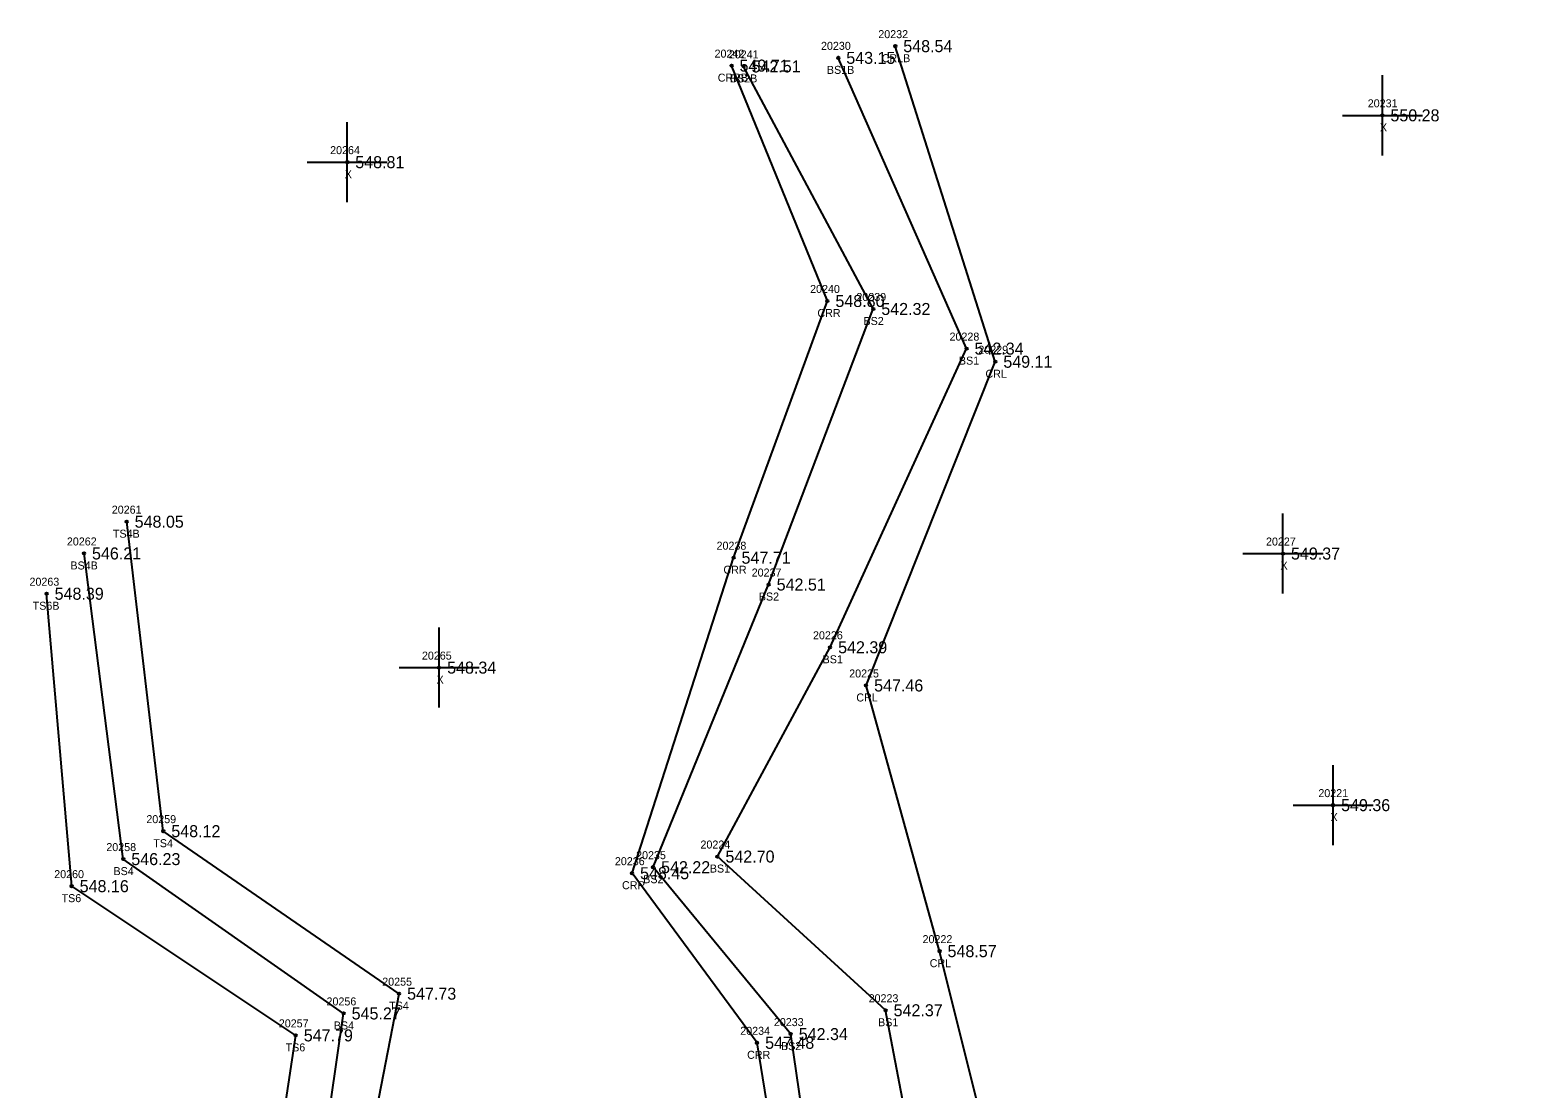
# Model space of a CAD drawing. Extents: x 1540443 to 1541844, y 887157 to 888162.
# Drawn here: x 1540987 to 1541174.7, y 888029.8 to 888162.1 of the extents above; entities that cross this region are included whole.
import ezdxf

# ---------------------------------------------------------------- set-up
doc = ezdxf.new("R2010")
doc.units = 0
for name, color, linetype in [('RD_DTM_BkLn2', 7, 'Continuous'), ('RD_DTM_BkLn_txCode', 7, 'Continuous'), ('RD_EX_H2O', 7, 'Continuous'), ('RD_EX_H2O_txCode', 7, 'Continuous'), ('RD_EX_Misc', 7, 'Continuous'), ('RD_EX_Misc_txCode', 7, 'Continuous'), ('RD_EX_TX_H2O_ELEV', 7, 'Continuous'), ('RD_EX_TX_Misc_ELEV', 7, 'Continuous'), ('RD_SMD_Locator', 7, 'Continuous')]:
    doc.layers.add(name, color=color, linetype=linetype)

msp = doc.modelspace()

# ---------------------------------------------------------------- linework, layer by layer
at = {"layer": 'RD_DTM_BkLn2'}
for points in [[(1541349.06, 887859.41), (1541301.9, 887838.51), (1541276.98, 887854.12), (1541250.17, 887847.68), (1541235.42, 887838.4), (1541226.46, 887818.66), (1541206.99, 887816.69), (1541177.91, 887783.05), (1541174.61, 887756.9), (1541155.39, 887744.58), (1541154.65, 887729.69), (1541126.74, 887754.56), (1541108.32, 887769.11), (1541148.46, 887831.42), (1541178.11, 887856.6), (1541159.66, 887905.22), (1541133.37, 887953.98), (1541101.85, 887998.23), (1541093.93, 888039.66), (1541072.92, 888058.86), (1541087, 888085), (1541104.04, 888122.31), (1541088.02, 888158.63)], [(1541146.1, 887665.49), (1541138.57, 887693.18), (1541134.72, 887704.76), (1541142.18, 887722.96), (1541114.88, 887744.39), (1541098.19, 887760.21), (1541108.65, 887794.85), (1541126.24, 887822.69), (1541166.01, 887866.51), (1541149.08, 887912.73), (1541115.84, 887949.01), (1541089.41, 887986.26), (1541082.08, 888036.68), (1541064.88, 888057.53), (1541079.32, 888092.84), (1541092.39, 888127.26), (1541076.18, 888157.56)], [(1541109.47, 887816.01), (1541103.08, 887823.18), (1541089.58, 887845.5), (1541085.67, 887875.78), (1541070.94, 887902.71), (1541055.37, 887955.36), (1541031.94, 887985.5), (1541025.96, 888004.59), (1541033.15, 888041.73), (1541003.69, 888062.03), (1540999.11, 888100.69)], [(1541106.04, 887811.91), (1541099.17, 887816.32), (1541082.8, 887844.85), (1541076.7, 887877.04), (1541064.39, 887901.43), (1541050.59, 887953.16), (1541026.43, 887984.19), (1541021.35, 888005.68), (1541026.22, 888039.26), (1540998.69, 888058.54), (1540993.78, 888096.72)], [(1541097.04, 887797.31), (1541091.49, 887816.39), (1541076.38, 887843.69), (1541072.19, 887876.18), (1541057.82, 887899.11), (1541044.09, 887950.3), (1541021.86, 887982.32), (1541015.45, 888004.75), (1541020.24, 888036.52), (1540992.24, 888055.16), (1540989.11, 888091.69)]]:
    msp.add_lwpolyline(points, dxfattribs=at)
at = {"layer": 'RD_EX_H2O'}
for points in [[(1541345.47, 887860.33), (1541299.81, 887843.04), (1541278.31, 887858.39), (1541248.14, 887850.88), (1541232.97, 887840.42), (1541206.44, 887819.7), (1541175.27, 887783.56), (1541168.89, 887762.72), (1541151.82, 887746.65), (1541151.42, 887737.55), (1541129.57, 887759.43), (1541125.03, 887781.17), (1541150.06, 887828.48), (1541182.67, 887854.92), (1541164.01, 887910.29), (1541139.24, 887954.07), (1541111.52, 888003.47), (1541100.67, 888047.04), (1541091.5, 888080.23), (1541107.64, 888120.67), (1541095.14, 888160.09)], [(1541139.32, 887662.55), (1541132.94, 887692.98), (1541127.99, 887710.83), (1541127.84, 887719.69), (1541112.29, 887736.27), (1541094.28, 887759.52), (1541097.04, 887797.31), (1541106.04, 887811.91), (1541109.47, 887816.01), (1541121.03, 887830.67), (1541155.26, 887878.19), (1541140.59, 887910.22), (1541112.01, 887944.26), (1541086.28, 887983.65), (1541077.88, 888035.59), (1541062.25, 888056.78), (1541074.93, 888096.19), (1541086.66, 888128.26), (1541074.68, 888157.66)]]:
    msp.add_lwpolyline(points, dxfattribs=at)
at = {"layer": 'RD_EX_Misc'}
for p, q in [((1541156, 888146.45), (1541156, 888156.45)), ((1541026.67, 888140.6), (1541026.67, 888150.6)), ((1541151, 888151.45), (1541161, 888151.45)), ((1541021.67, 888145.6), (1541031.67, 888145.6)), ((1541143.58, 888091.71), (1541143.58, 888101.71)), ((1541138.58, 888096.71), (1541148.58, 888096.71)), ((1541038.15, 888077.46), (1541038.15, 888087.46)), ((1541033.15, 888082.46), (1541043.15, 888082.46)), ((1541149.84, 888060.28), (1541149.84, 888070.28)), ((1541144.84, 888065.28), (1541154.84, 888065.28))]:
    msp.add_line(p, q, dxfattribs=at)
at = {"layer": 'RD_SMD_Locator'}
for centre in [(1541095.14, 888160.09), (1541074.68, 888157.66), (1541076.18, 888157.56), (1541088.02, 888158.63), (1541156, 888151.45), (1541026.67, 888145.6), (1541086.66, 888128.26), (1541092.39, 888127.26), (1541104.04, 888122.31), (1541107.64, 888120.67), (1540999.11, 888100.69), (1540993.78, 888096.72), (1541074.93, 888096.19), (1541143.58, 888096.71), (1541079.32, 888092.84), (1540989.11, 888091.69), (1541087, 888085), (1541038.15, 888082.46), (1541091.5, 888080.23), (1541149.84, 888065.28), (1541003.69, 888062.03), (1540998.69, 888058.54), (1541072.92, 888058.86), (1541062.25, 888056.78), (1541064.88, 888057.53), (1540992.24, 888055.16), (1541100.67, 888047.04), (1541033.15, 888041.73), (1541026.22, 888039.26), (1541093.93, 888039.66), (1541020.24, 888036.52), (1541077.88, 888035.59), (1541082.08, 888036.68)]:
    msp.add_circle(centre, 0.15, dxfattribs=at)

# ---------------------------------------------------------------- texts
at = {"layer": 'RD_DTM_BkLn_txCode'}
for s, p in [('20241', (1541074.34, 888158.56)), ('20230', (1541085.86, 888159.63)), ('BS1B', (1541086.6, 888156.63)), ('BS2B', (1541074.48, 888155.56)), ('20239', (1541090.28, 888128.26)), ('BS2', (1541091.17, 888125.26)), ('20228', (1541101.92, 888123.31)), ('BS1', (1541103.09, 888120.31)), ('20261', (1540997.25, 888101.69)), ('TS4B', (1540997.39, 888098.69)), ('20262', (1540991.64, 888097.72)), ('BS4B', (1540992.08, 888094.72)), ('20237', (1541077.2, 888093.84)), ('20263', (1540986.97, 888092.69)), ('TS6B', (1540987.37, 888089.69)), ('BS2', (1541078.09, 888090.84)), ('20226', (1541084.86, 888086)), ('BS1', (1541086.06, 888083)), ('20259', (1541001.57, 888063.03)), ('20258', (1540996.57, 888059.54)), ('TS4', (1541002.44, 888060.03)), ('20224', (1541070.8, 888059.86)), ('20235', (1541062.76, 888058.53)), ('20260', (1540990.06, 888056.16)), ('BS4', (1540997.46, 888056.54)), ('BS2', (1541063.65, 888055.53)), ('BS1', (1541071.97, 888056.86)), ('TS6', (1540990.98, 888053.16)), ('20255', (1541031.04, 888042.73)), ('20256', (1541024.08, 888040.26)), ('20223', (1541091.81, 888040.66)), ('TS4', (1541031.91, 888039.73)), ('20257', (1541018.12, 888037.52)), ('BS4', (1541024.99, 888037.26)), ('20233', (1541079.97, 888037.68)), ('BS1', (1541092.99, 888037.66)), ('BS2', (1541080.86, 888034.68)), ('TS6', (1541018.97, 888034.52))]:
    msp.add_text(s, height=1, dxfattribs=at).set_placement(p)
at = {"layer": 'RD_EX_H2O_txCode'}
for s, p in [('20232', (1541093.02, 888161.09)), ('20242', (1541072.56, 888158.66)), ('CRLB', (1541093.44, 888158.09)), ('CRRB', (1541072.96, 888155.66)), ('20240', (1541084.5, 888129.26)), ('CRR', (1541085.41, 888126.26)), ('20229', (1541105.52, 888121.67)), ('CRL', (1541106.41, 888118.67)), ('20238', (1541072.81, 888097.19)), ('CRR', (1541073.67, 888094.19)), ('20225', (1541089.38, 888081.23)), ('CRL', (1541090.27, 888078.23)), ('20236', (1541060.11, 888057.78)), ('CRR', (1541061, 888054.78)), ('20222', (1541098.55, 888048.04)), ('CRL', (1541099.44, 888045.04)), ('20234', (1541075.77, 888036.59)), ('CRR', (1541076.63, 888033.59))]:
    msp.add_text(s, height=1, dxfattribs=at).set_placement(p)
at = {"layer": 'RD_EX_Misc_txCode'}
for s, p in [('20231', (1541154.17, 888152.45)), ('X', (1541155.69, 888149.45)), ('20264', (1541024.53, 888146.6)), ('X', (1541026.36, 888143.6)), ('20227', (1541141.46, 888097.71)), ('X', (1541143.27, 888094.71)), ('20265', (1541036, 888083.46)), ('X', (1541037.83, 888080.46)), ('20221', (1541148, 888066.28)), ('X', (1541149.52, 888063.28))]:
    msp.add_text(s, height=1, dxfattribs=at).set_placement(p)
at = {"layer": 'RD_EX_TX_H2O_ELEV'}
for s, p in [('548.54', (1541096.14, 888159.34)), ('549.71', (1541075.68, 888156.91)), ('548.80', (1541087.66, 888127.51)), ('549.11', (1541108.64, 888119.92)), ('547.71', (1541075.93, 888095.44)), ('547.46', (1541092.5, 888079.48)), ('548.45', (1541063.25, 888056.03)), ('548.57', (1541101.67, 888046.29)), ('547.48', (1541078.88, 888034.84))]:
    msp.add_text(s, height=1.5, dxfattribs=at).set_placement(p)
at = {"layer": 'RD_EX_TX_Misc_ELEV'}
for s, p in [('542.51', (1541077.18, 888156.81)), ('543.15', (1541089.02, 888157.88)), ('550.28', (1541157, 888150.7)), ('548.81', (1541027.67, 888144.85)), ('542.32', (1541093.39, 888126.51)), ('542.34', (1541105.04, 888121.56)), ('548.05', (1541000.11, 888099.94)), ('546.21', (1540994.78, 888095.97)), ('549.37', (1541144.58, 888095.96)), ('548.39', (1540990.11, 888090.94)), ('542.51', (1541080.32, 888092.09)), ('542.39', (1541088, 888084.25)), ('548.34', (1541039.15, 888081.71)), ('549.36', (1541150.84, 888064.53)), ('548.12', (1541004.69, 888061.28)), ('546.23', (1540999.69, 888057.79)), ('542.22', (1541065.88, 888056.78)), ('542.70', (1541073.92, 888058.11)), ('548.16', (1540993.24, 888054.41)), ('547.73', (1541034.15, 888040.98)), ('545.27', (1541027.22, 888038.51)), ('542.37', (1541094.93, 888038.91)), ('547.79', (1541021.24, 888035.77)), ('542.34', (1541083.08, 888035.93))]:
    msp.add_text(s, height=1.5, dxfattribs=at).set_placement(p)

doc.saveas('drawing.dxf')
